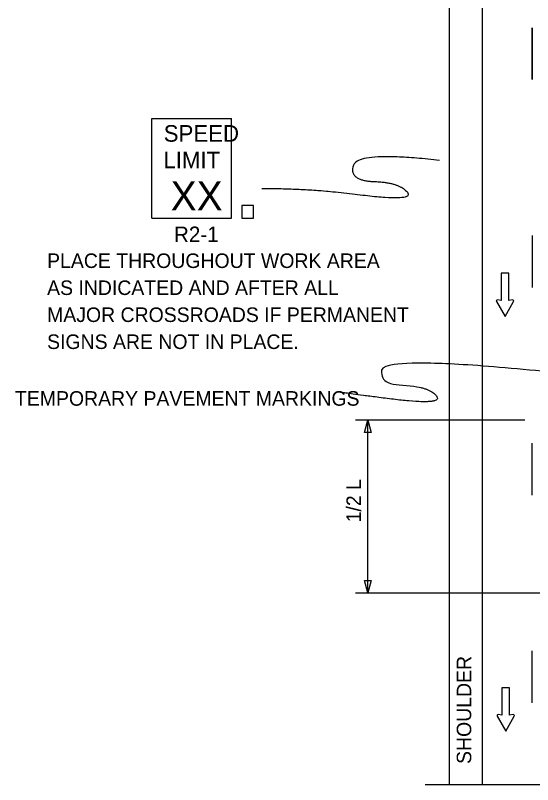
# Model space of a CAD drawing. Extents: x 16726 to 19504, y 5932 to 7446.
# Drawn here: x 16729.9 to 16978.9, y 6079.7 to 6450.1 of the extents above; entities that cross this region are included whole.
import ezdxf

# ---------------------------------------------------------------- set-up
doc = ezdxf.new("R2010")
doc.units = 0
for name, color, linetype in [('ALI_LEGAL_EX', 7, 'Continuous'), ('MT_SCRATCH_LEVEL_E', 7, 'Continuous'), ('PAVT_EDGE_EX', 7, 'Continuous'), ('TRAFFIC_SIGNS_PR', 7, 'Continuous'), ('TYPICAL_EX', 7, 'Continuous'), ('TYPICAL_TEXT_DIMEN_PR', 7, 'Continuous')]:
    doc.layers.add(name, color=color, linetype=linetype)

msp = doc.modelspace()

# ---------------------------------------------------------------- linework, layer by layer
at = {"layer": 'ALI_LEGAL_EX'}
for points in [[(16978.71, 6419.12), (16978.71, 6444.12)], [(16978.95, 6419.12), (16978.95, 6444.12)], [(16978.95, 6319.12), (16978.95, 6344.12)], [(16978.71, 6219.12), (16978.71, 6244.12)], [(16978.71, 6119.12), (16978.71, 6144.12)]]:
    msp.add_lwpolyline(points, dxfattribs=at)
at = {"layer": 'MT_SCRATCH_LEVEL_E'}
for p, q in [((16967.52, 6326), (16963.78, 6326)), ((16963.78, 6326), (16963.78, 6312.74)), ((16967.52, 6326), (16963.78, 6326)), ((16963.78, 6326), (16963.78, 6312.74)), ((16967.52, 6312.74), (16967.52, 6326)), ((16967.52, 6312.74), (16967.52, 6326)), ((16961.52, 6312.37), (16965.67, 6305.13)), ((16961.52, 6312.37), (16965.67, 6305.13)), ((16963.78, 6312.74), (16962, 6313.05)), ((16963.78, 6312.74), (16962, 6313.05)), ((16965.67, 6305.13), (16969.78, 6312.37)), ((16965.67, 6305.13), (16969.78, 6312.37)), ((16969.3, 6313.05), (16967.52, 6312.74)), ((16969.3, 6313.05), (16967.52, 6312.74)), ((16967.87, 6126.36), (16964.13, 6126.36)), ((16964.13, 6126.36), (16964.13, 6113.11)), ((16967.87, 6126.36), (16964.13, 6126.36)), ((16964.13, 6126.36), (16964.13, 6113.11)), ((16967.87, 6113.11), (16967.87, 6126.36)), ((16967.87, 6113.11), (16967.87, 6126.36)), ((16961.87, 6112.74), (16966.02, 6105.5)), ((16961.87, 6112.74), (16966.02, 6105.5)), ((16964.13, 6113.11), (16962.35, 6113.42)), ((16964.13, 6113.11), (16962.35, 6113.42)), ((16966.02, 6105.5), (16970.13, 6112.74)), ((16966.02, 6105.5), (16970.13, 6112.74)), ((16969.65, 6113.42), (16967.87, 6113.11)), ((16969.65, 6113.42), (16967.87, 6113.11))]:
    msp.add_line(p, q, dxfattribs=at)
for centre, start, end in [((16961.93, 6312.59), 80.0362, 209.7731), ((16961.93, 6312.59), 80.0362, 209.7731), ((16969.37, 6312.6), 330.4248, 99.9638), ((16969.37, 6312.6), 330.4248, 99.9638), ((16962.28, 6112.96), 80.0362, 209.7731), ((16962.28, 6112.96), 80.0362, 209.7731), ((16969.72, 6112.96), 330.4248, 99.9638), ((16969.72, 6112.96), 330.4248, 99.9638)]:
    msp.add_arc(centre, 0.463, start, end, dxfattribs=at)
at = {"layer": 'PAVT_EDGE_EX'}
for p, q in [((16954.71, 6865.32), (16954.71, 6079.93)), ((16938.71, 6770.67), (16938.71, 6079.72))]:
    msp.add_line(p, q, dxfattribs=at)
at = {"layer": 'TRAFFIC_SIGNS_PR'}
for p, q in [((16795.55, 6400.38), (16833.95, 6400.38)), ((16795.55, 6352.38), (16795.55, 6400.38)), ((16833.95, 6352.38), (16833.95, 6400.38)), ((16795.55, 6352.38), (16833.95, 6352.38))]:
    msp.add_line(p, q, dxfattribs=at)
msp.add_lwpolyline([(16838.97, 6352.38), (16844.56, 6352.38), (16844.56, 6358.55), (16838.97, 6358.55)], close=True, dxfattribs=at)
at = {"layer": 'TYPICAL_EX'}
msp.add_line((16938.71, 6865.32), (16938.71, 6080.34), dxfattribs=at)
at = {"layer": 'TYPICAL_TEXT_DIMEN_PR'}
for p, q in [((16975.25, 6255.13), (16893.7, 6255.13)), ((16898.02, 6249.26), (16899.59, 6255.13)), ((16899.59, 6172.09), (16899.59, 6255.13)), ((16899.59, 6255.13), (16901.16, 6249.26)), ((16899.59, 6249.26), (16898.02, 6249.26)), ((16901.16, 6249.26), (16899.59, 6249.26)), ((16899.62, 6172.07), (16898.06, 6177.94)), ((16898.06, 6177.94), (16899.62, 6177.94)), ((16899.62, 6177.94), (16901.19, 6177.94)), ((16901.19, 6177.94), (16899.62, 6172.07)), ((16893.7, 6172.07), (17040.9, 6172.07)), ((16927.17, 6079.72), (17115.16, 6079.72))]:
    msp.add_line(p, q, dxfattribs=at)
for points in [[(16934.16, 6380.2), (16894.67, 6384.85), (16890.42, 6370.53), (16914.91, 6369.62), (16922.32, 6360.23), (16870.57, 6366.8), (16848.51, 6366.53)], [(17002.21, 6276.96), (16908.69, 6286.73), (16904.45, 6272.41), (16928.94, 6271.51), (16936.35, 6262.11), (16884.59, 6268.69), (16886.54, 6268.69)]]:
    msp.add_open_spline(points, degree=2, dxfattribs=at)

# ---------------------------------------------------------------- texts
at = {"layer": 'TRAFFIC_SIGNS_PR'}
for s, height, p in [('SPEED', 8, (16801.32, 6389.24)), ('LIMIT', 8, (16801.16, 6376.44)), ('XX', 14.031, (16804.66, 6356.14)), ('R2-1', 7.44, (16806.23, 6340.94)), ('PLACE THROUGHOUT WORK AREA', 7, (16745.16, 6328.45)), ('AS INDICATED AND AFTER ALL', 7, (16745.16, 6315.45)), ('MAJOR CROSSROADS IF PERMANENT', 7, (16745.16, 6302.45)), ('SIGNS ARE NOT IN PLACE.', 7, (16745.16, 6289.45))]:
    msp.add_text(s, height=height, dxfattribs=at).set_placement(p)
at = {"layer": 'TYPICAL_TEXT_DIMEN_PR'}
msp.add_text('TEMPORARY PAVEMENT MARKINGS', height=7, dxfattribs=at).set_placement((16729.68, 6262.15))
for s, p in [('1/2 L', (16896.3, 6205.99)), ('SHOULDER', (16949.4, 6089.67))]:
    msp.add_text(s, height=7, rotation=90, dxfattribs=at).set_placement(p)

doc.saveas('drawing.dxf')
